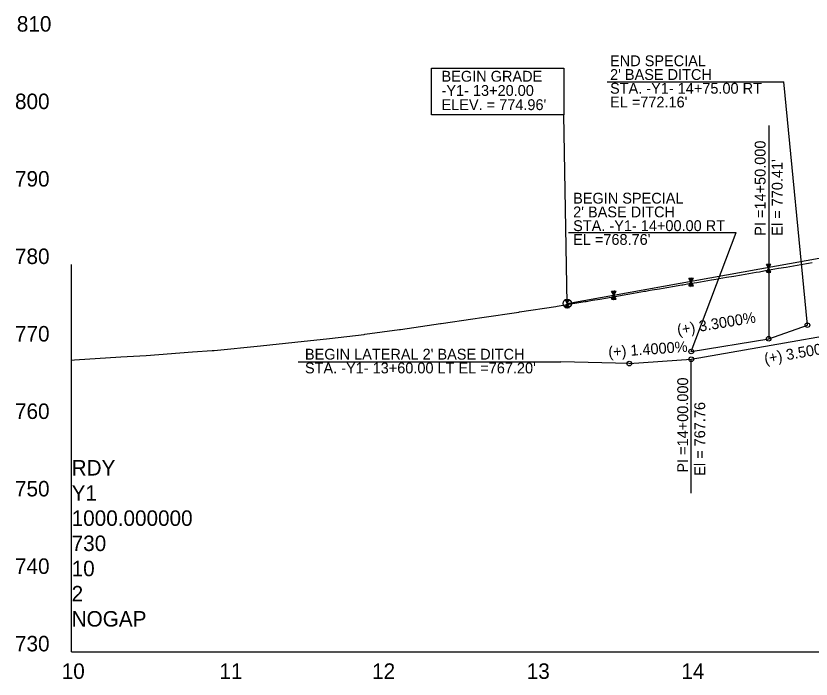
# Model space of a CAD drawing. Extents: x 579185 to 595036, y -53221 to -44640.
# Drawn here: x 579285 to 579799, y -48575 to -48147 of the extents above; entities that cross this region are included whole.
import ezdxf

# ---------------------------------------------------------------- set-up
doc = ezdxf.new("R2010")
doc.units = 0
for name, color, linetype in [('Exist Profile Cell', 7, 'Continuous'), ('Exist Vertical Profile Ground Line', 7, 'Continuous'), ('Exist Vertical Profile Horizontal Axis Label Major', 7, 'Continuous'), ('Exist Vertical Profile Vertical Axis Label', 7, 'Continuous'), ('Old_Level_2', 7, 'Continuous'), ('Prop Grid Mask', 7, 'Continuous'), ('Prop Vertical Profile Curve Label', 7, 'Continuous'), ('Prop Vertical Profile Ditch Grade Left', 7, 'Continuous'), ('Prop Vertical Profile Ditch Grade Left Label', 7, 'Continuous'), ('Prop Vertical Profile Ditch Grade Right', 7, 'Continuous'), ('Prop Vertical Profile Ditch Grade Right Label', 7, 'Continuous'), ('Prop Vertical Profile Grade', 7, 'Continuous'), ('Prop VPI Ditch Grade Left Label', 7, 'Continuous'), ('Prop VPI Ditch Grade Right Label', 7, 'Continuous'), ('Prop VPI Label', 7, 'Continuous')]:
    doc.layers.add(name, color=color, linetype=linetype)

msp = doc.modelspace()

# ---------------------------------------------------------------- linework, layer by layer
at = {"layer": 'Exist Profile Cell'}
for q in [(579321.48, -48307.09), (581829.78, -48557.09), (579321.48, -48557.09)]:
    msp.add_line((579321.48, -48557.09), q, dxfattribs=at)
at = {"layer": 'Exist Vertical Profile Ground Line'}
msp.add_lwpolyline([(579321.48, -48368.81), (579323.38, -48368.73), (579353.33, -48366.82), (579369.59, -48365.79), (579399.49, -48363.6), (579412.17, -48362.67), (579413.14, -48362.65), (579413.45, -48362.58), (579443.43, -48359.68), (579465.66, -48357.31), (579487.91, -48354.92), (579510.42, -48352.25), (579510.83, -48352.19), (579533.2, -48349.08), (579533.86, -48348.99), (579559.66, -48345.19), (579560.04, -48345.13), (579580.47, -48342.11), (579586.32, -48341.25), (579610.19, -48337.85), (579610.59, -48337.79), (579634.05, -48334.21), (579634.95, -48334.07), (579652.9, -48331.06), (579653.58, -48330.94), (579657.71, -48330.24), (579662.52, -48329.44), (579667.32, -48328.63), (579670.84, -48328.04), (579672.13, -48327.8), (579673.52, -48327.55), (579676.94, -48326.95), (579681.75, -48326.1), (579686.55, -48325.26), (579691.36, -48324.42), (579692.28, -48324.26), (579693.98, -48323.94), (579696.17, -48323.57), (579700.97, -48322.76), (579705.78, -48321.95), (579710.59, -48321.15), (579714.15, -48320.55), (579715.4, -48320.31), (579716.02, -48320.2), (579720.2, -48319.49), (579725.01, -48318.69), (579729.82, -48317.88), (579734.63, -48317.08), (579736.06, -48316.84), (579738.79, -48316.35), (579739.43, -48316.24), (579744.24, -48315.42), (579749.05, -48314.59), (579753.85, -48313.77), (579758.66, -48312.95), (579763.47, -48312.13), (579765.51, -48311.78), (579768.36, -48311.28), (579770.58, -48310.88), (579773.08, -48310.45), (579777.89, -48309.61), (579782.7, -48308.78), (579787.51, -48307.95), (579792.31, -48307.12), (579797.19, -48306.27), (579799.51, -48305.86)], dxfattribs=at)
at = {"layer": 'Old_Level_2'}
for p, q in [((579771.48, -48309.53), (579770.04, -48307.03)), ((579770.04, -48307.03), (579772.93, -48307.03)), ((579770.52, -48307.86), (579772.45, -48307.86)), ((579771.48, -48309.53), (579772.93, -48307.03)), ((579770.04, -48312.03), (579771.48, -48309.53)), ((579770.04, -48312.03), (579772.93, -48312.03)), ((579770.52, -48311.2), (579772.45, -48311.2)), ((579771, -48308.7), (579771.96, -48308.7)), ((579771, -48310.36), (579771.96, -48310.36)), ((579772.93, -48312.03), (579771.48, -48309.53)), ((579721.48, -48318.38), (579720.04, -48315.88)), ((579720.04, -48315.88), (579722.93, -48315.88)), ((579720.04, -48320.88), (579721.48, -48318.38)), ((579720.52, -48316.71), (579722.45, -48316.71)), ((579721, -48317.55), (579721.96, -48317.55)), ((579721.48, -48318.38), (579722.93, -48315.88)), ((579722.93, -48320.88), (579721.48, -48318.38)), ((579720.04, -48320.88), (579722.93, -48320.88)), ((579720.52, -48320.05), (579722.45, -48320.05)), ((579721, -48319.21), (579721.96, -48319.21)), ((579671.48, -48326.96), (579670.04, -48324.46)), ((579670.04, -48324.46), (579672.93, -48324.46)), ((579670.04, -48329.46), (579671.48, -48326.96)), ((579670.52, -48325.29), (579672.45, -48325.29)), ((579670.52, -48328.63), (579672.45, -48328.63)), ((579671, -48326.13), (579671.96, -48326.13)), ((579671, -48327.79), (579671.96, -48327.79)), ((579671.48, -48326.96), (579672.93, -48324.46)), ((579672.93, -48329.46), (579671.48, -48326.96)), ((579641.48, -48332.29), (579640.04, -48329.79)), ((579640.04, -48329.79), (579642.93, -48329.79)), ((579640.04, -48334.79), (579641.48, -48332.29)), ((579640.52, -48330.62), (579642.45, -48330.62)), ((579641, -48331.46), (579641.96, -48331.46)), ((579641, -48333.12), (579641.96, -48333.12)), ((579641.48, -48332.29), (579642.93, -48329.79)), ((579642.93, -48334.79), (579641.48, -48332.29)), ((579670.04, -48329.46), (579672.93, -48329.46)), ((579640.04, -48334.79), (579642.93, -48334.79)), ((579640.52, -48333.96), (579642.45, -48333.96))]:
    msp.add_line(p, q, dxfattribs=at)
at = {"layer": 'Prop Grid Mask'}
msp.add_lwpolyline([(579553.74, -48180.38), (579639.14, -48180.38), (579639.14, -48210.56), (579553.74, -48210.56)], close=True, dxfattribs=at)
at = {"layer": 'Prop Vertical Profile Curve Label'}
msp.add_line((579641.48, -48332.29), (579639.14, -48210.56), dxfattribs=at)
at = {"layer": 'Prop Vertical Profile Ditch Grade Left'}
msp.add_lwpolyline([(579681.48, -48371.09), (579721.48, -48368.29), (579871.48, -48342.04), (579971.48, -48314.54), (580021.48, -48292.44)], dxfattribs=at)
at = {"layer": 'Prop Vertical Profile Ditch Grade Left Label'}
for p, q in [((579721.48, -48454.63), (579721.48, -48368.29)), ((579467.64, -48369.89), (579637.34, -48369.89)), ((579681.48, -48371.09), (579637.34, -48369.89))]:
    msp.add_line(p, q, dxfattribs=at)
for centre in [(579681.48, -48371.09), (579721.48, -48368.29)]:
    msp.add_circle(centre, 1.5, dxfattribs=at)
at = {"layer": 'Prop Vertical Profile Ditch Grade Right'}
msp.add_lwpolyline([(579721.48, -48363.29), (579771.48, -48355.04), (579796.48, -48346.29)], dxfattribs=at)
at = {"layer": 'Prop Vertical Profile Ditch Grade Right Label'}
for p, q in [((579667.2, -48189.34), (579781.28, -48189.34)), ((579796.48, -48346.29), (579781.28, -48189.34)), ((579771.57, -48217.46), (579771.48, -48312.53)), ((579771.57, -48259.97), (579771.48, -48355.04)), ((579642.35, -48286.59), (579750.46, -48286.59)), ((579721.48, -48363.29), (579750.46, -48286.59))]:
    msp.add_line(p, q, dxfattribs=at)
at = {"layer": 'Prop Vertical Profile Grade'}
msp.add_line((579641.48, -48332.29), (579806.48, -48302.67), dxfattribs=at)
at = {"layer": 'Prop VPI Ditch Grade Right Label'}
for centre in [(579796.48, -48346.29), (579771.48, -48355.04), (579721.48, -48363.29)]:
    msp.add_circle(centre, 1.5, dxfattribs=at)
at = {"layer": 'Prop VPI Label'}
msp.add_circle((579641.48, -48332.29), 2.75, dxfattribs=at)

# ---------------------------------------------------------------- texts
at = {"layer": 'Exist Profile Cell'}
for s, p in [('RDY', (579321.48, -48443.34)), ('Y1', (579321.48, -48459.59)), ('1000.000000', (579321.48, -48475.84)), ('730', (579321.48, -48492.09)), ('10', (579321.48, -48508.34)), ('2', (579321.48, -48524.59)), ('NOGAP', (579321.48, -48540.84))]:
    msp.add_text(s, height=10, dxfattribs=at).set_placement(p)
at = {"layer": 'Exist Vertical Profile Horizontal Axis Label Major'}
for s, p in [('10', (579315.07, -48574.59)), ('11', (579416.9, -48574.59)), ('12', (579515.45, -48574.59)), ('13', (579615.29, -48574.59)), ('14', (579715.13, -48574.59))]:
    msp.add_text(s, height=10, dxfattribs=at).set_placement(p)
at = {"layer": 'Exist Vertical Profile Vertical Axis Label'}
for s, p in [('810', (579286.11, -48156.84)), ('800', (579284.91, -48206.84)), ('790', (579284.91, -48256.84)), ('780', (579284.91, -48306.84)), ('770', (579284.91, -48356.84)), ('760', (579284.91, -48406.84)), ('750', (579284.91, -48456.84)), ('740', (579284.91, -48506.84)), ('730', (579284.91, -48556.84))]:
    msp.add_text(s, height=10, dxfattribs=at).set_placement(p)
at = {"layer": 'Old_Level_2'}
for p in [(579771.25, -48306.87), (579771.06, -48313.03), (579721.25, -48315.72), (579671.25, -48324.3), (579721.06, -48321.88), (579641.25, -48329.63), (579671.06, -48330.46), (579641.06, -48335.79)]:
    msp.add_text('6"', height=0.8, dxfattribs=at).set_placement(p)
at = {"layer": 'Prop Vertical Profile Ditch Grade Left Label'}
for s, rotation, p in [('(+) 1.4000%', 4.0042, (579668.17, -48367.08)), ('(+) 3.5000%', 9.9262, (579769.25, -48371.39))]:
    msp.add_text(s, height=7, rotation=rotation, dxfattribs=at).set_placement(p)
for s, p in [("BEGIN LATERAL 2' BASE DITCH", (579472.11, -48368.54)), ("STA. -Y1- 13+60.00 LT EL =767.20'", (579472.11, -48377.41))]:
    msp.add_text(s, height=7, dxfattribs=at).set_placement(p)
at = {"layer": 'Prop Vertical Profile Ditch Grade Right'}
for s, p in [('END SPECIAL ', (579669.07, -48179.16)), ("2' BASE DITCH", (579669.07, -48188.03)), ('STA. -Y1- 14+75.00 RT ', (579669.07, -48196.9)), ("EL =772.16'", (579669.07, -48205.78)), ('BEGIN SPECIAL ', (579645.24, -48267.84)), ("2' BASE DITCH", (579645.24, -48276.71)), ('STA. -Y1- 14+00.00 RT ', (579645.24, -48285.58)), ("EL =768.76'", (579645.24, -48294.46))]:
    msp.add_text(s, height=7, dxfattribs=at).set_placement(p)
at = {"layer": 'Prop Vertical Profile Ditch Grade Right Label'}
msp.add_text('(+) 3.3000%', height=7, rotation=9.3694, dxfattribs=at).set_placement((579712.97, -48352.84))
at = {"layer": 'Prop VPI Ditch Grade Left Label'}
for s, p in [('PI =14+00.000', (579719.48, -48441.48)), ('El = 767.76', (579730.48, -48443.51))]:
    msp.add_text(s, height=7, rotation=90, dxfattribs=at).set_placement(p)
at = {"layer": 'Prop VPI Ditch Grade Right Label'}
for s, p in [('PI =14+50.000', (579769.48, -48288.58)), ("El = 770.41'", (579780.48, -48288.58))]:
    msp.add_text(s, height=7, rotation=90, dxfattribs=at).set_placement(p)
at = {"layer": 'Prop VPI Label'}
for s, p in [('BEGIN GRADE', (579560.29, -48189.14)), ('-Y1- 13+20.00', (579560.29, -48198.31)), ("ELEV. = 774.96'", (579560.29, -48207.49))]:
    msp.add_text(s, height=7, dxfattribs=at).set_placement(p)

doc.saveas('drawing.dxf')
